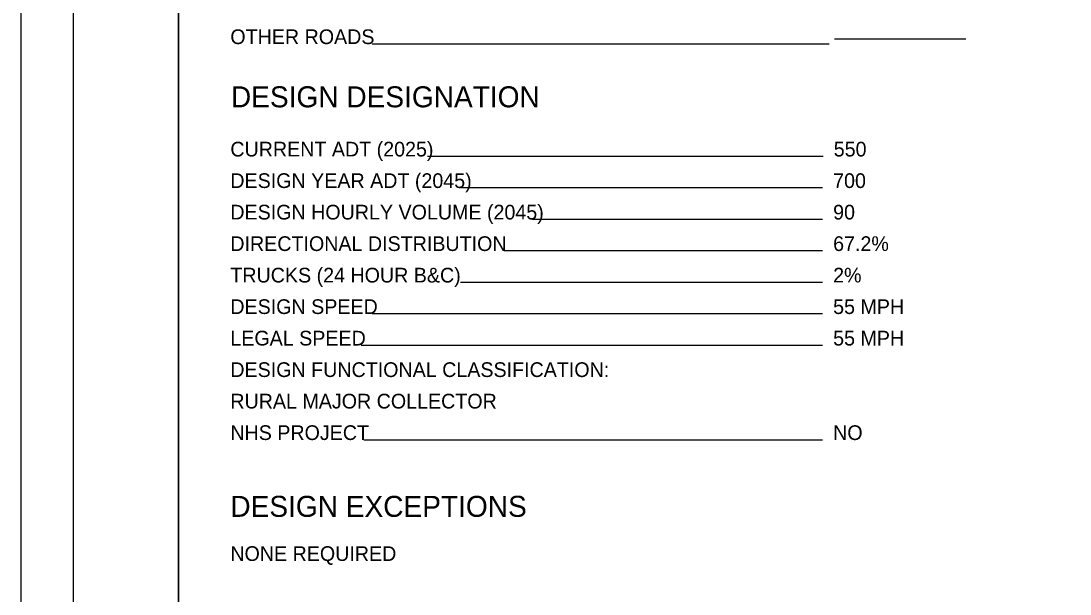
# Model space of a CAD drawing. Extents: x -2.1 to 31.9, y 6.3 to 28.3.
# Drawn here: x -2.07 to 7.93, y 11.98 to 17.44 of the extents above; entities that cross this region are included whole.
import ezdxf

# ---------------------------------------------------------------- set-up
doc = ezdxf.new("R2010")
doc.units = 0
for name, color, linetype in [('SH_Border', 7, 'Continuous'), ('SH_Cut_Line', 7, 'Continuous'), ('SH_Data', 7, 'Continuous'), ('SH_Text', 7, 'Continuous')]:
    doc.layers.add(name, color=color, linetype=linetype)

msp = doc.modelspace()

# ---------------------------------------------------------------- linework, layer by layer
at = {"layer": 'SH_Border'}
for points in [[(-1.5656, 27.844), (-0.5656, 27.844), (-0.5656, 6.844), (-1.5656, 6.844)], [(-0.5656, 27.844), (31.4344, 27.844), (31.4344, 6.844), (-0.5656, 6.844)]]:
    msp.add_lwpolyline(points, close=True, dxfattribs=at)
at = {"layer": 'SH_Cut_Line'}
msp.add_lwpolyline([(-2.0656, 6.344), (31.9344, 6.344), (31.9344, 28.344), (-2.0656, 28.344)], close=True, dxfattribs=at)
at = {"layer": 'SH_Data'}
for p, q in [((5.6344, 17.2206), (1.2815, 17.2206)), ((6.9344, 17.2663), (5.6844, 17.2663)), ((5.5769, 16.1502), (1.8055, 16.1502)), ((5.5713, 15.8502), (2.1229, 15.8502)), ((5.5713, 15.5502), (2.8068, 15.5502)), ((5.5713, 15.2502), (2.5381, 15.2502)), ((5.5713, 14.9502), (2.1229, 14.9502)), ((5.5713, 14.6502), (1.2804, 14.6502)), ((5.5713, 14.3502), (1.1766, 14.3502)), ((5.5713, 13.4502), (1.2014, 13.4502))]:
    msp.add_line(p, q, dxfattribs=at)

# ---------------------------------------------------------------- texts
msp.add_text('DESIGN DESIGNATION', height=0.2, dxfattribs=at).set_placement((-0.0656, 16.6186))
at = {"layer": 'SH_Text'}
for s, height, p in [('OTHER ROADS', 0.14, (-0.0711, 17.2206)), ('CURRENT ADT (2025)', 0.14, (-0.0711, 16.1502)), ('550', 0.14, (5.6769, 16.1502)), ('DESIGN YEAR ADT (2045)', 0.14, (-0.0711, 15.8502)), ('700', 0.14, (5.6713, 15.8502)), ('DESIGN HOURLY VOLUME (2045)', 0.14, (-0.0711, 15.5502)), ('90', 0.14, (5.6713, 15.5502)), ('DIRECTIONAL DISTRIBUTION', 0.14, (-0.0711, 15.2502)), ('67.2%', 0.14, (5.6713, 15.2502)), ('TRUCKS (24 HOUR B&C)', 0.14, (-0.0711, 14.9502)), ('2%', 0.14, (5.6713, 14.9502)), ('DESIGN SPEED', 0.14, (-0.0711, 14.6502)), ('55 MPH', 0.14, (5.6713, 14.6502)), ('LEGAL SPEED', 0.14, (-0.0711, 14.3502)), ('55 MPH', 0.14, (5.6713, 14.3502)), ('DESIGN FUNCTIONAL CLASSIFICATION:', 0.14, (-0.0711, 14.0502)), ('RURAL MAJOR COLLECTOR', 0.14, (-0.0711, 13.7502)), ('NHS PROJECT', 0.14, (-0.0711, 13.4502)), ('NO', 0.14, (5.6713, 13.4502)), ('DESIGN EXCEPTIONS', 0.2, (-0.0711, 12.7184)), ('NONE REQUIRED', 0.14, (-0.0711, 12.2984))]:
    msp.add_text(s, height=height, dxfattribs=at).set_placement(p)

doc.saveas('drawing.dxf')
